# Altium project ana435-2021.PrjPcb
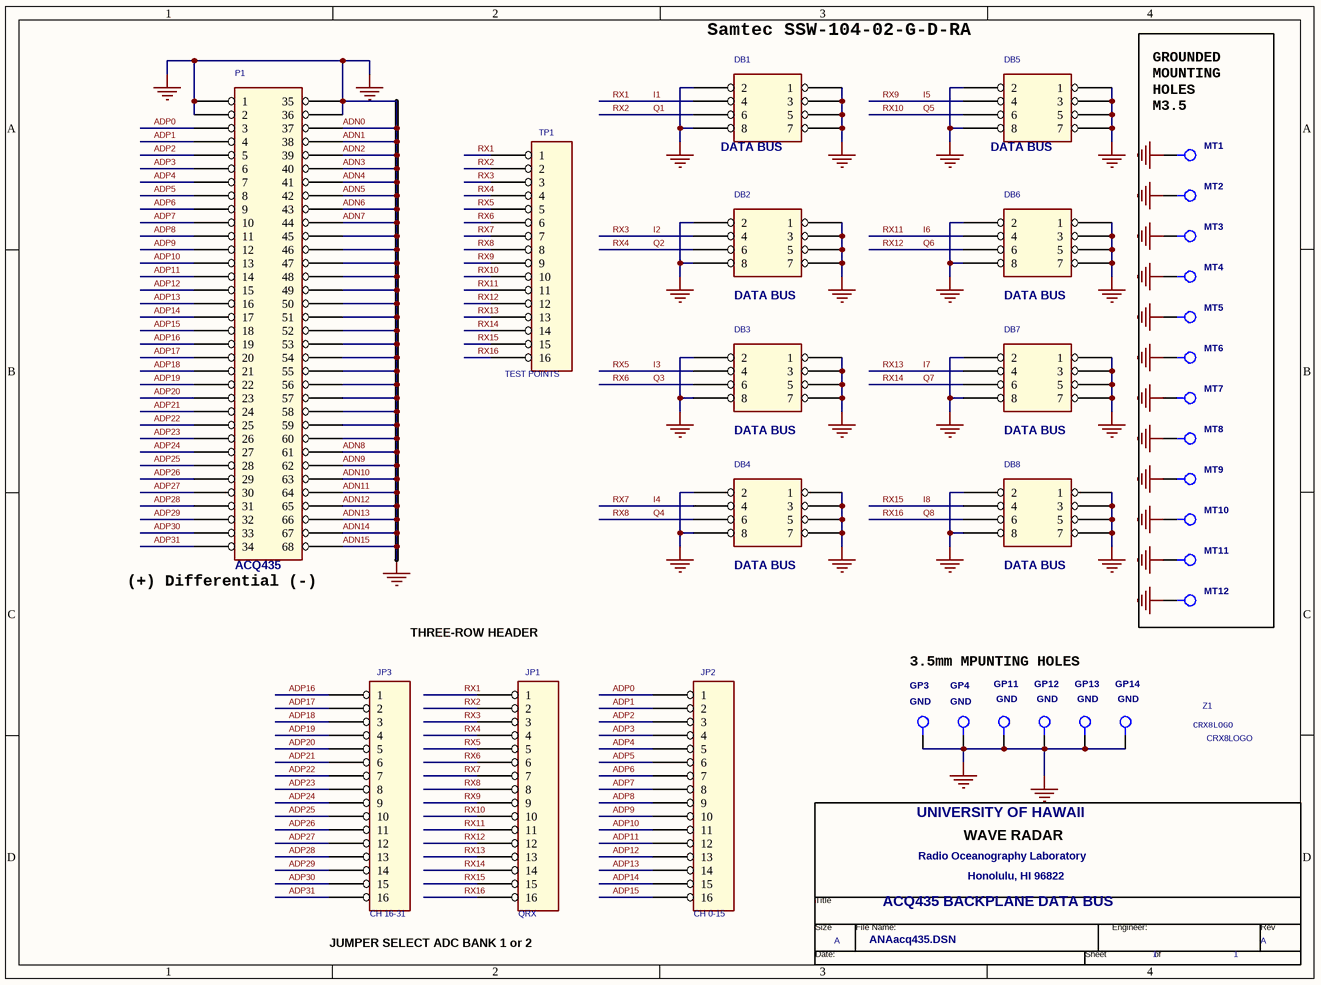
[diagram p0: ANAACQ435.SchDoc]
1 sheet, 33 parts. Net scope: global (net labels, ports and power ports of the same name join across sheets).
Board file: ANA435-2021.PcbDoc

## Sheet ANAACQ435.SchDoc
size 246 x 182 mm; Organization: Altium Limited; Address1: L3, 12a Rodborough Rd; Address2: Frenchs Forest; Address3: NSW; Address4: Australia 2086

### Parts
*  Page Count: 1  Page Size: A  OrgAddr3: Honolulu, HI 96822  OrgAddr1: Radio Oceanography Laboratory  OrgName: UNIVERSITY OF HAWAII  Title: ACQ435 BACKPLANE DATA BUS  Doc: ANAacq435.DSN  (hidden comment: HWRadar)  (graphical)
DB1  DATA BUS  [TSW-4X2F]
DB2  DATA BUS  [TSW-4X2F]
DB3  DATA BUS  [TSW-4X2F]
DB4  DATA BUS  [TSW-4X2F]
DB5  DATA BUS  [TSW-4X2F]
DB6  DATA BUS  [TSW-4X2F]
DB7  DATA BUS  [TSW-4X2F]
DB8  DATA BUS  [TSW-4X2F]
GP3  GND  [TP]
GP4  GND  [TP]
GP11  GND  [TP]
GP12  GND  [TP]
GP13  GND  [TP]
GP14  GND  [TP]
JP1  QRX  [SIP16]
JP2  CH 0-15  [SIP16]
JP3  CH 16-31  [SIP16]
MT1  GND  [TP]  (value not drawn)
MT2  GND  [TP]  (value not drawn)
MT3  GND  [TP]  (value not drawn)
MT4  GND  [TP]  (value not drawn)
MT5  GND  [TP]  (value not drawn)
MT6  GND  [TP]  (value not drawn)
MT7  GND  [TP]  (value not drawn)
MT8  GND  [TP]  (value not drawn)
MT9  GND  [TP]  (value not drawn)
MT10  GND  [TP]  (value not drawn)
MT11  GND  [TP]  (value not drawn)
MT12  GND  [TP]  (value not drawn)
P1  ACQ435  [MDR68]
TP1  TEST POINTS  [SIP16]
Z1  CRX8LOGO  [CRX8TINY]

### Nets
ADN0: DB1.1 DB1.2 DB1.3 DB1.5 DB1.7 DB1.8 DB2.1 DB2.2 DB2.3 DB2.5 DB2.7 DB2.8 DB3.1 DB3.2 DB3.3 DB3.5 DB3.7 DB3.8 DB4.1 DB4.2 DB4.3 DB4.5 DB4.7 DB4.8 DB5.1 DB5.2 DB5.3 DB5.5 DB5.7 DB5.8 DB6.1 DB6.2 DB6.3 DB6.5 DB6.7 DB6.8 DB7.1 DB7.2 DB7.3 DB7.5 DB7.7 DB7.8 DB8.1 DB8.2 DB8.3 DB8.5 DB8.7 DB8.8 GP3.1(TP) GP4.1(TP) GP11.1(TP) GP12.1(TP) GP13.1(TP) GP14.1(TP) MT1.1(TP) MT2.1(TP) MT3.1(TP) MT4.1(TP) MT5.1(TP) MT6.1(TP) MT7.1(TP) MT8.1(TP) MT9.1(TP) MT10.1(TP) MT11.1(TP) MT12.1(TP) P1.1 P1.2 P1.35 P1.36 P1.37 P1.38 P1.39 P1.40 P1.41 P1.42 P1.43 P1.44 P1.45 P1.46 P1.47 P1.48 P1.49 P1.50 P1.51 P1.52 P1.53 P1.54 P1.55 P1.56 P1.57 P1.58 P1.59 P1.60 P1.61 P1.62 P1.63 P1.64 P1.65 P1.66 P1.67 P1.68  [also labelled ADN1, ADN10, ADN11, ADN12, ADN13, ADN14, ADN15, ADN2, ADN3, ADN4, ADN5, ADN6, ADN7, ADN8, ADN9, GND]
ADP0: JP2.1 P1.3
ADP1: JP2.2 P1.4
ADP2: JP2.3 P1.5
ADP3: JP2.4 P1.6
ADP4: JP2.5 P1.7
ADP5: JP2.6 P1.8
ADP6: JP2.7 P1.9
ADP7: JP2.8 P1.10
ADP8: JP2.9 P1.11
ADP9: JP2.10 P1.12
ADP10: JP2.11 P1.13
ADP11: JP2.12 P1.14
ADP12: JP2.13 P1.15
ADP13: JP2.14 P1.16
ADP14: JP2.15 P1.17
ADP15: JP2.16 P1.18
ADP16: JP3.1 P1.19
ADP17: JP3.2 P1.20
ADP18: JP3.3 P1.21
ADP19: JP3.4 P1.22
ADP20: JP3.5 P1.23
ADP21: JP3.6 P1.24
ADP22: JP3.7 P1.25
ADP23: JP3.8 P1.26
ADP24: JP3.9 P1.27
ADP25: JP3.10 P1.28
ADP26: JP3.11 P1.29
ADP27: JP3.12 P1.30
ADP28: JP3.13 P1.31
ADP29: JP3.14 P1.32
ADP30: JP3.15 P1.33
ADP31: JP3.16 P1.34
I1: DB1.4 JP1.1 TP1.1  [also labelled RX1]
I2: DB2.4 JP1.3 TP1.3  [also labelled RX3]
I3: DB3.4 JP1.5 TP1.5  [also labelled RX5]
I4: DB4.4 JP1.7 TP1.7  [also labelled RX7]
I5: DB5.4 JP1.9 TP1.9  [also labelled RX9]
I6: DB6.4 JP1.11 TP1.11  [also labelled RX11]
I7: DB7.4 JP1.13 TP1.13  [also labelled RX13]
I8: DB8.4 JP1.15 TP1.15  [also labelled RX15]
Q1: DB1.6 JP1.2 TP1.2  [also labelled RX2]
Q2: DB2.6 JP1.4 TP1.4  [also labelled RX4]
Q3: DB3.6 JP1.6 TP1.6  [also labelled RX6]
Q4: DB4.6 JP1.8 TP1.8  [also labelled RX8]
Q5: DB5.6 JP1.10 TP1.10  [also labelled RX10]
Q6: DB6.6 JP1.12 TP1.12  [also labelled RX12]
Q7: DB7.6 JP1.14 TP1.14  [also labelled RX14]
Q8: DB8.6 JP1.16 TP1.16  [also labelled RX16]

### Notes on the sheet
- (near DB1) Samtec SSW-104-02-G-D-RA
- (near MT1) GROUNDED
  MOUNTING
  HOLES
  M3.5
- (near P1) (+) Differential (-)
- THREE-ROW HEADER
- 3.5mm MPUNTING HOLES
- JUMPER SELECT ADC BANK 1 or 2

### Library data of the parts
* = HWRadar: OrgAddr2: 2525 Correa Road; Engineer:: <ENG>
DB1-DB8 = HEADER 4X2: MFR: Samtec; MFR PART: SSW-104-02-G-D-RA; DK Stock: SAM1215-04-ND
GP3 GP4 GP11-GP14 = TP_1: MFR PART: DNI; DK Stock: n/s
JP1-JP3 = HEADER 16: MFR: TE Connectivity; MFR PART: 1-534237-4; DK Stock: A26426-ND
MT1-MT12 = TP_1: DK Stock: DNI
P1 = MDR68: MFR: Molex; MFR PART: 737760201; DK Stock: WM7304-ND
TP1 = HEADER 16: MFR PART: DNI
Z1 = CRX8LOGO: MFR PART: DNI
